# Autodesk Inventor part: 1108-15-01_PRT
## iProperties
Created: 2007-03
Part Number: 1108-15-01_PRT
Document SubType Name: Modeling
Designer: Andy Moles
Material: ABS Plastic
Mass: 0.836448 g
Surface Area: 13.6999 cm^2
Volume: 0.789102 cm^3
Density: 1.06 g/cm^3
Author: Andy Moles
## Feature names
1. Extrusion1
